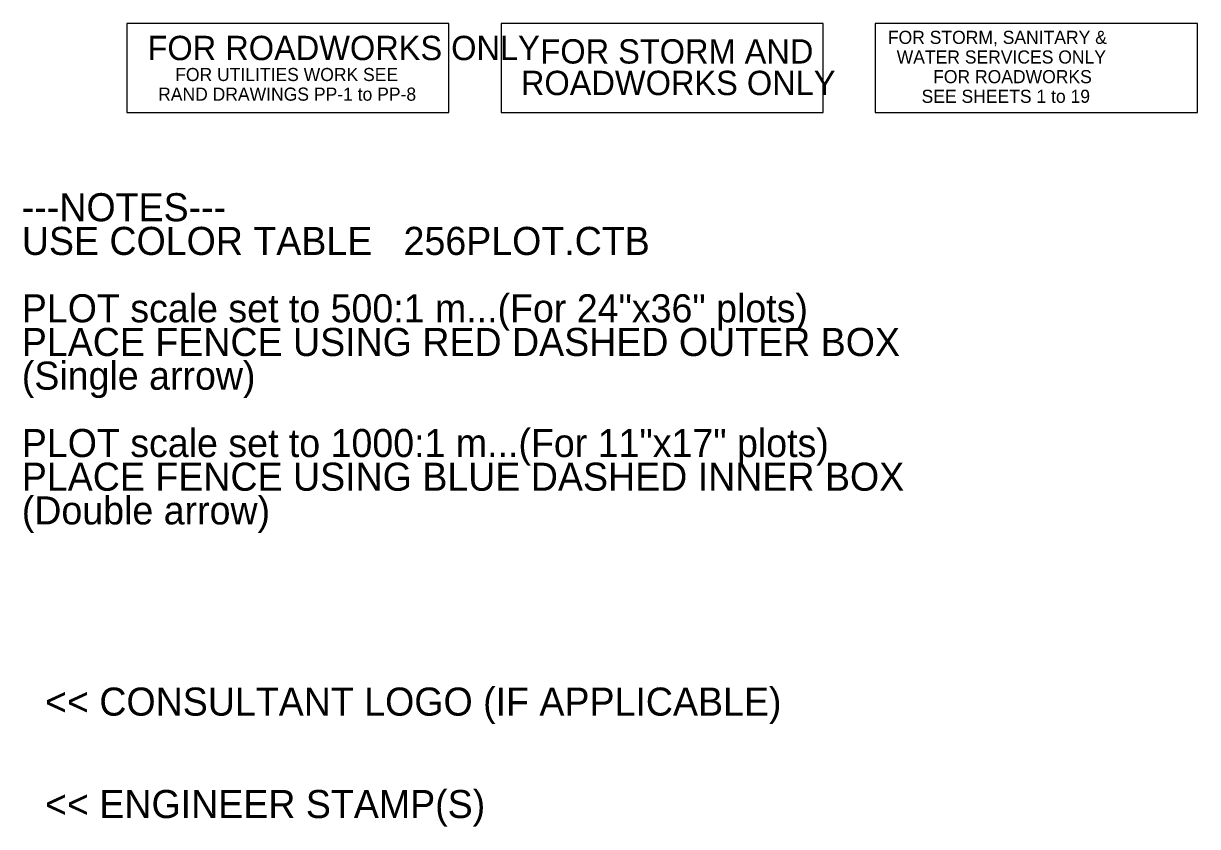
# Model space of a CAD drawing. Extents: x 595568 to 603709, y 4837996 to 4846716.
# Drawn here: x 603395.8 to 603709.4, y 4846396.7 to 4846611.3 of the extents above; entities that cross this region are included whole.
import ezdxf

# ---------------------------------------------------------------- set-up
doc = ezdxf.new("R2010")
doc.units = 0
for name, color, linetype in [('ENG_LEGEND', 7, 'Continuous'), ('ENG_TX_LEGEND', 7, 'Continuous'), ('ENG_WK_MISC-1', 7, 'Continuous')]:
    doc.layers.add(name, color=color, linetype=linetype)

msp = doc.modelspace()

# ---------------------------------------------------------------- linework, layer by layer
at = {"layer": 'ENG_LEGEND'}
for points in [[(603423.34, 4846587.51), (603509.42, 4846587.51), (603509.42, 4846611.25), (603423.34, 4846611.25)], [(603523.34, 4846587.51), (603609.42, 4846587.51), (603609.42, 4846611.25), (603523.34, 4846611.25)], [(603623.34, 4846587.51), (603709.42, 4846587.51), (603709.42, 4846611.25), (603623.34, 4846611.25)]]:
    msp.add_lwpolyline(points, close=True, dxfattribs=at)

# ---------------------------------------------------------------- texts
at = {"layer": 'ENG_TX_LEGEND'}
for s, height, p in [('FOR ROADWORKS ONLY', 6.5, (603428.9, 4846601.46)), ('FOR STORM AND', 6.5, (603533.87, 4846600.55)), ('FOR STORM, SANITARY &', 3.5, (603626.69, 4846605.8)), ('WATER SERVICES ONLY', 3.5, (603629.05, 4846600.55)), ('FOR UTILITIES WORK SEE', 3.5, (603436.3, 4846595.87)), ('ROADWORKS ONLY', 6.5, (603528.66, 4846592.12)), ('FOR ROADWORKS', 3.5, (603638.79, 4846595.3)), ('RAND DRAWINGS PP-1 to PP-8', 3.5, (603431.74, 4846590.62)), ('SEE SHEETS 1 to 19', 3.5, (603635.7, 4846590.05))]:
    msp.add_text(s, height=height, rotation=360, dxfattribs=at).set_placement(p)
at = {"layer": 'ENG_WK_MISC-1'}
for s, p in [('---NOTES---', (603395.32, 4846558.41)), ('USE COLOR TABLE   256PLOT.CTB', (603395.32, 4846549.41)), ('PLOT scale set to 500:1 m...(For 24"x36" plots)', (603395.32, 4846531.41)), ('PLACE FENCE USING RED DASHED OUTER BOX', (603395.32, 4846522.41)), ('(Single arrow)', (603395.32, 4846513.41)), ('PLOT scale set to 1000:1 m...(For 11"x17" plots)', (603395.32, 4846495.41)), ('PLACE FENCE USING BLUE DASHED INNER BOX', (603395.32, 4846486.41)), ('(Double arrow)', (603395.32, 4846477.41)), ('<< CONSULTANT LOGO (IF APPLICABLE)', (603401.53, 4846426.32)), ('<< ENGINEER STAMP(S)', (603401.53, 4846398.95))]:
    msp.add_text(s, height=7.5, dxfattribs=at).set_placement(p)

doc.saveas('drawing.dxf')
